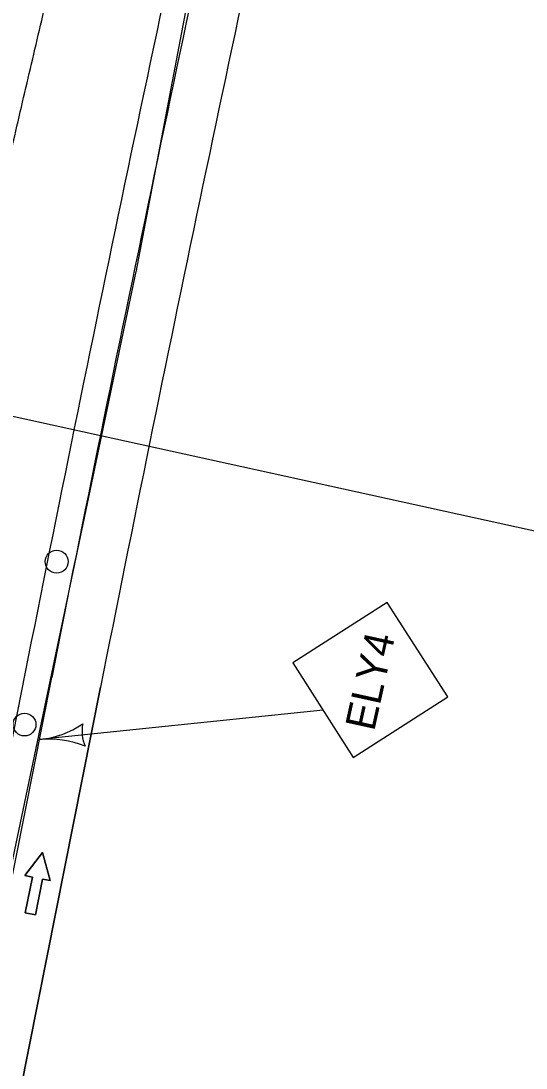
# Model space of a CAD drawing. Extents: x 14104283 to 14120882, y 8635219 to 8671666.
# Drawn here: x 14108015.7 to 14108137.4, y 8639915.4 to 8640167.7 of the extents above; entities that cross this region are included whole.
import ezdxf

# ---------------------------------------------------------------- set-up
doc = ezdxf.new("R2010")
doc.units = 0
for name, color, linetype in [('Cell', 7, 'Continuous'), ('dsnNonPlotable', 7, 'Continuous'), ('dsnPaintPlaceEdgeLineLeftYellow', 7, 'Continuous'), ('dsnPaintPlaceEdgeLineRightWhite', 7, 'Continuous'), ('dsnPaintRemoveDoubleCenterLineYellow', 7, 'Continuous'), ('dsnShadingPaved', 7, 'Continuous'), ('dsnStdLabel', 7, 'Continuous')]:
    doc.layers.add(name, color=color, linetype=linetype)

msp = doc.modelspace()

# ---------------------------------------------------------------- linework, layer by layer
at = {"layer": 'Cell'}
msp.add_lwpolyline([(14108019.18, 8639952.34), (14108016.72, 8639952.83), (14108018.44, 8639961.41), (14108016.6, 8639961.78), (14108020.89, 8639967.3), (14108022.73, 8639960.55), (14108020.89, 8639960.92)], close=True, dxfattribs=at)
msp.add_lwpolyline([(14108020.89, 8639960.92), (14108022.73, 8639960.55), (14108020.89, 8639967.3), (14108016.6, 8639961.78), (14108018.44, 8639961.41), (14108016.72, 8639952.83), (14108019.18, 8639952.34), (14108020.89, 8639960.92)], dxfattribs=at)
for centre in [(14108024.29, 8640037.4), (14108016.55, 8639998.15)]:
    msp.add_circle(centre, 2.75, dxfattribs=at)
at = {"layer": 'dsnNonPlotable'}
msp.add_lwpolyline([(14107218.44, 8638642.33), (14107554.83, 8640173.31), (14108541.3, 8639956.56), (14108204.91, 8638425.58)], close=True, dxfattribs=at)
at = {"layer": 'dsnPaintPlaceEdgeLineLeftYellow'}
msp.add_line((14107968.56, 8639734.67), (14108023.1, 8640009.51), dxfattribs=at)
msp.add_arc((14119581.23, 8637715.91), 11783.5, 167.610212, 168.776036, dxfattribs=at)
at = {"layer": 'dsnPaintPlaceEdgeLineRightWhite'}
msp.add_line((14107980.33, 8639732.33), (14108034.87, 8640007.17), dxfattribs=at)
for radius in [11783.5, 11771.5]:
    msp.add_arc((14119581.23, 8637715.91), radius, 167.610212, 168.776036, dxfattribs=at)
at = {"layer": 'dsnPaintRemoveDoubleCenterLineYellow'}
for p, q in [((14108093.95, 8640372.57), (14108043.37, 8640107.11)), ((14107998.36, 8639892.54), (14108043.42, 8640107.32))]:
    msp.add_line(p, q, dxfattribs=at)
at = {"layer": 'dsnShadingPaved'}
for p, q in [((14108016.73, 8640010.77), (14107962.19, 8639735.93)), ((14107968.56, 8639734.67), (14108023.1, 8640009.51)), ((14108034.87, 8640007.17), (14107980.33, 8639732.33))]:
    msp.add_line(p, q, dxfattribs=at)
for radius in [11790, 11783.5, 11771.5]:
    msp.add_arc((14119581.23, 8637715.91), radius, 167.610212, 168.776036, dxfattribs=at)
msp.add_open_spline([(14107997.15, 8640065.69), (14107997.85, 8640068.79), (14107999.25, 8640074.98), (14108001.36, 8640084.27), (14108003.48, 8640093.55), (14108005.61, 8640102.84), (14108007.74, 8640112.12), (14108009.88, 8640121.4), (14108012.03, 8640130.68), (14108014.18, 8640139.95), (14108016.35, 8640149.23), (14108018.52, 8640158.5), (14108020.7, 8640167.77), (14108022.88, 8640177.04), (14108025.07, 8640186.31), (14108027.27, 8640195.57), (14108029.48, 8640204.83), (14108031.7, 8640214.1), (14108033.92, 8640223.35), (14108036.15, 8640232.61), (14108038.39, 8640241.87), (14108039.88, 8640248.03), (14108040.63, 8640251.12)], degree=3, dxfattribs=at)
at = {"layer": 'dsnStdLabel'}
msp.add_line((14108088.48, 8640001.61), (14108020.13, 8639994.52), dxfattribs=at)
msp.add_lwpolyline([(14108095.76, 8639990.24), (14108118.5, 8640004.79), (14108103.95, 8640027.54), (14108081.21, 8640012.99)], close=True, dxfattribs=at)
for centre, radius, start, end in [((14108017.76, 8640017.35), 22.95, 275.922, 303.9932), ((14108039.27, 8639996.51), 8.86, 168.1878, 203.6562), ((14108022.5, 8639971.7), 22.95, 67.8508, 95.9221)]:
    msp.add_arc(centre, radius, start, end, dxfattribs=at)

# ---------------------------------------------------------------- texts
msp.add_text('ELY4', height=7.2, rotation=77.6078, dxfattribs=at).set_placement((14108100.78, 8639996.34))

doc.saveas('drawing.dxf')
